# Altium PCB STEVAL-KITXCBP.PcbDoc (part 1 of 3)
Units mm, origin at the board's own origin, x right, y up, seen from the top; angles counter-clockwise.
Board outline 265 x 224 mm, 4 copper layers (Top Layer, GND, PWR, Bottom Layer), stack 1.55 mm thick; 241 components, 114 nets, 595 pads, 236 vias.
Unrouted connection lines stored in the file: 2.
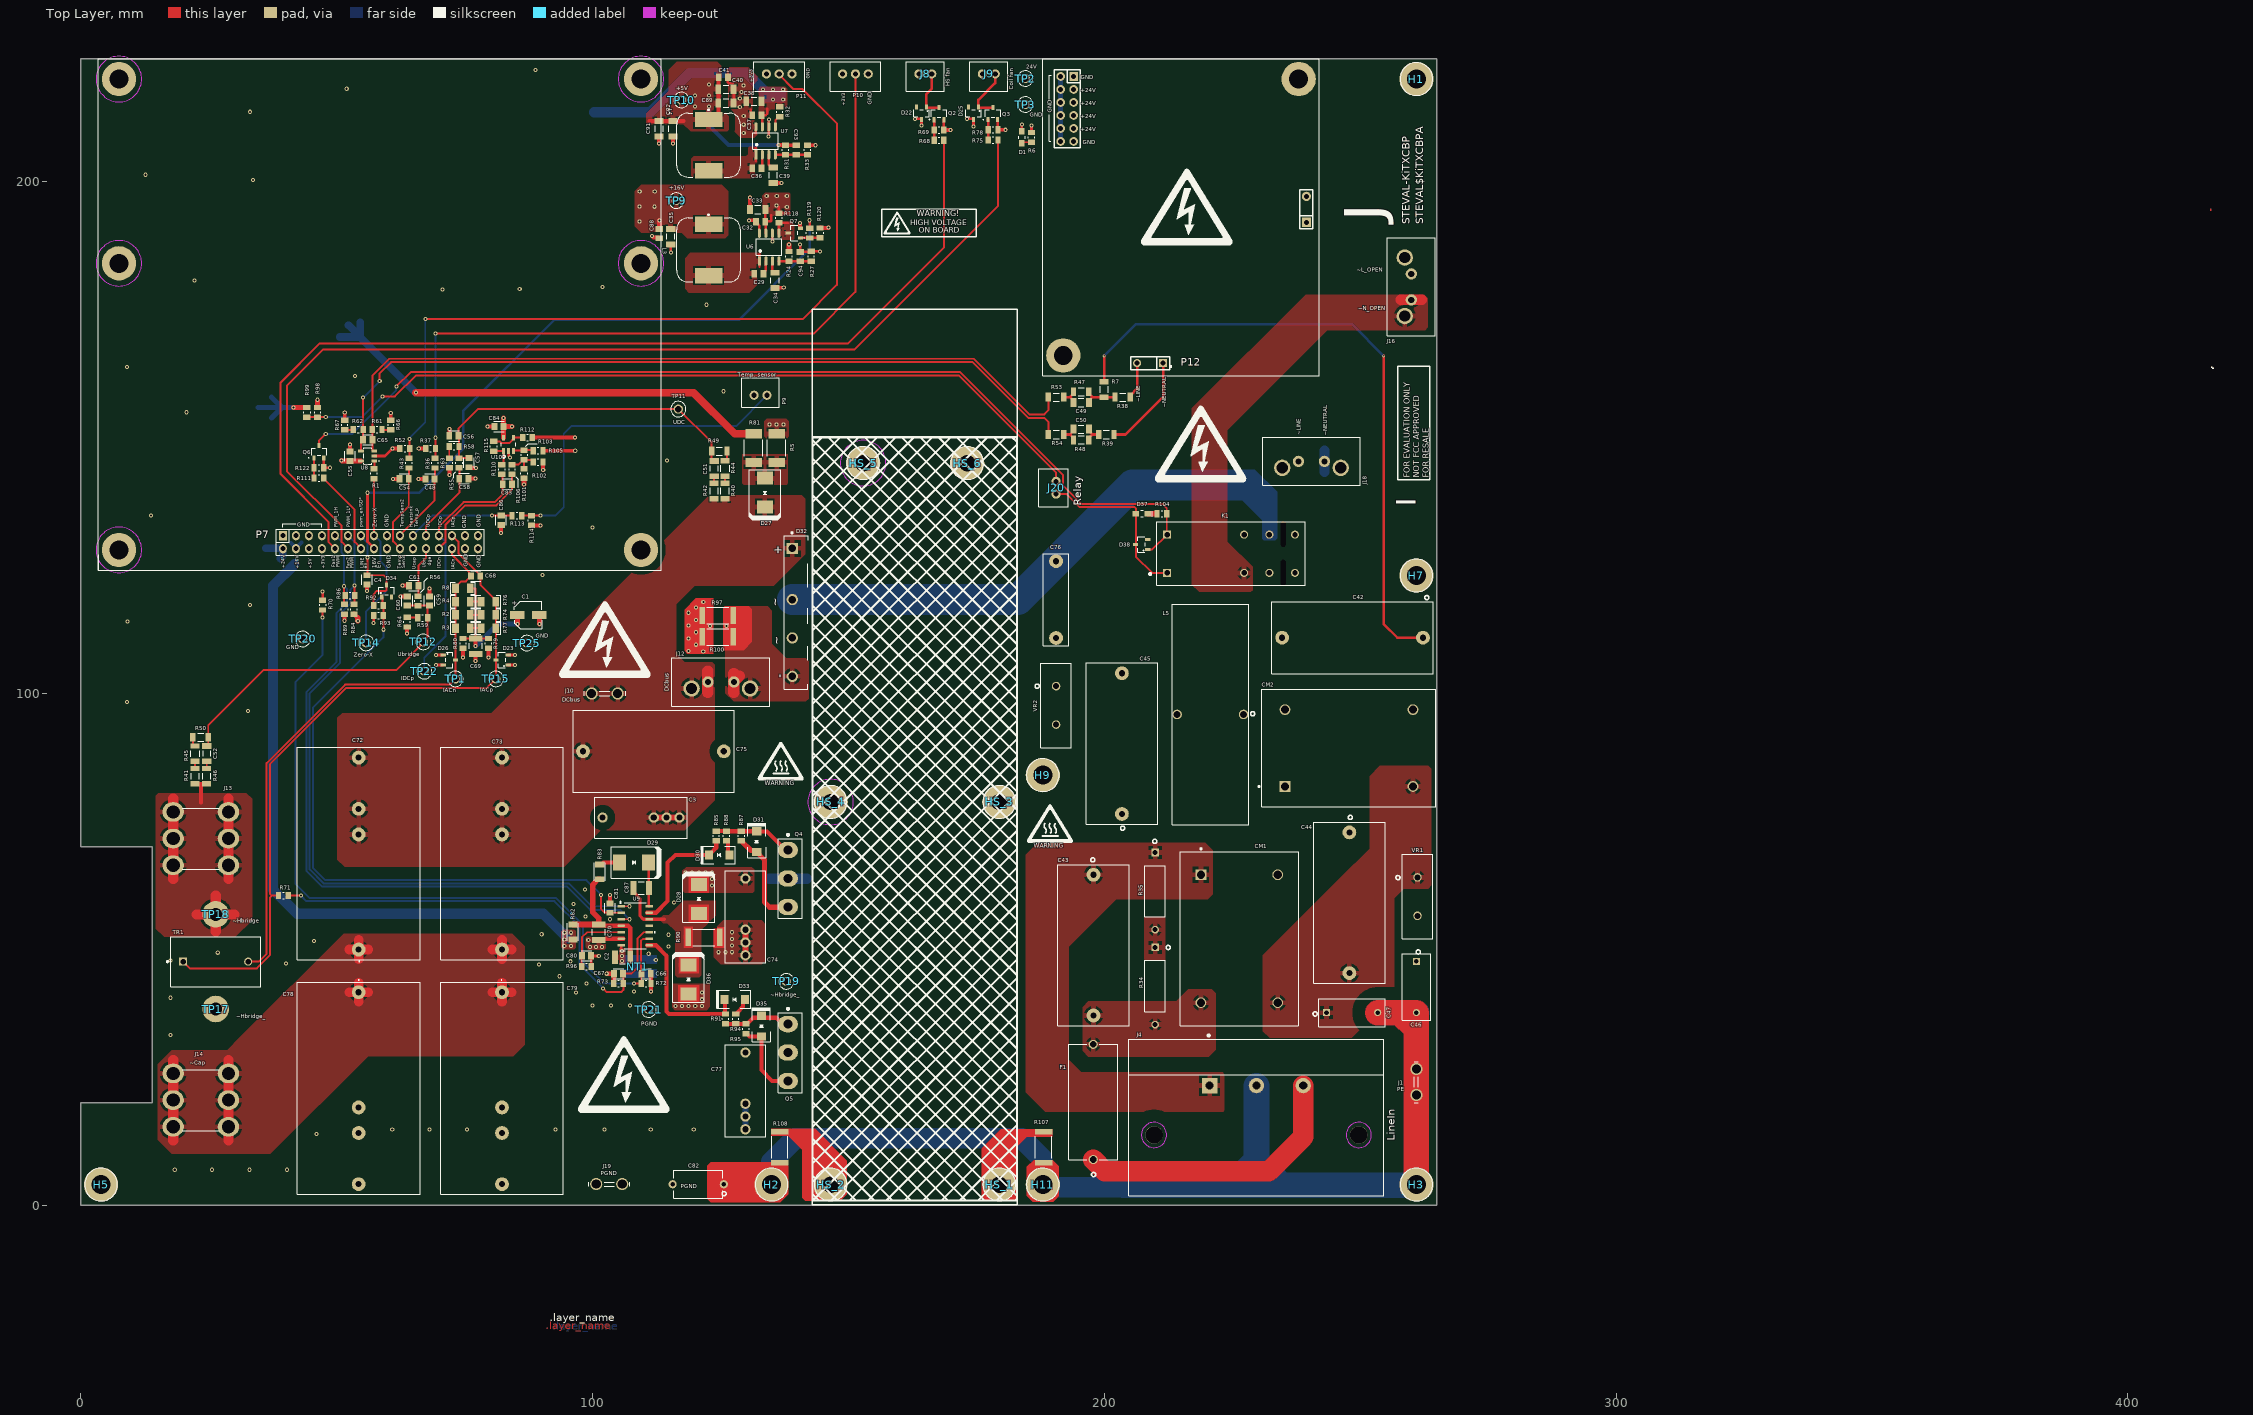
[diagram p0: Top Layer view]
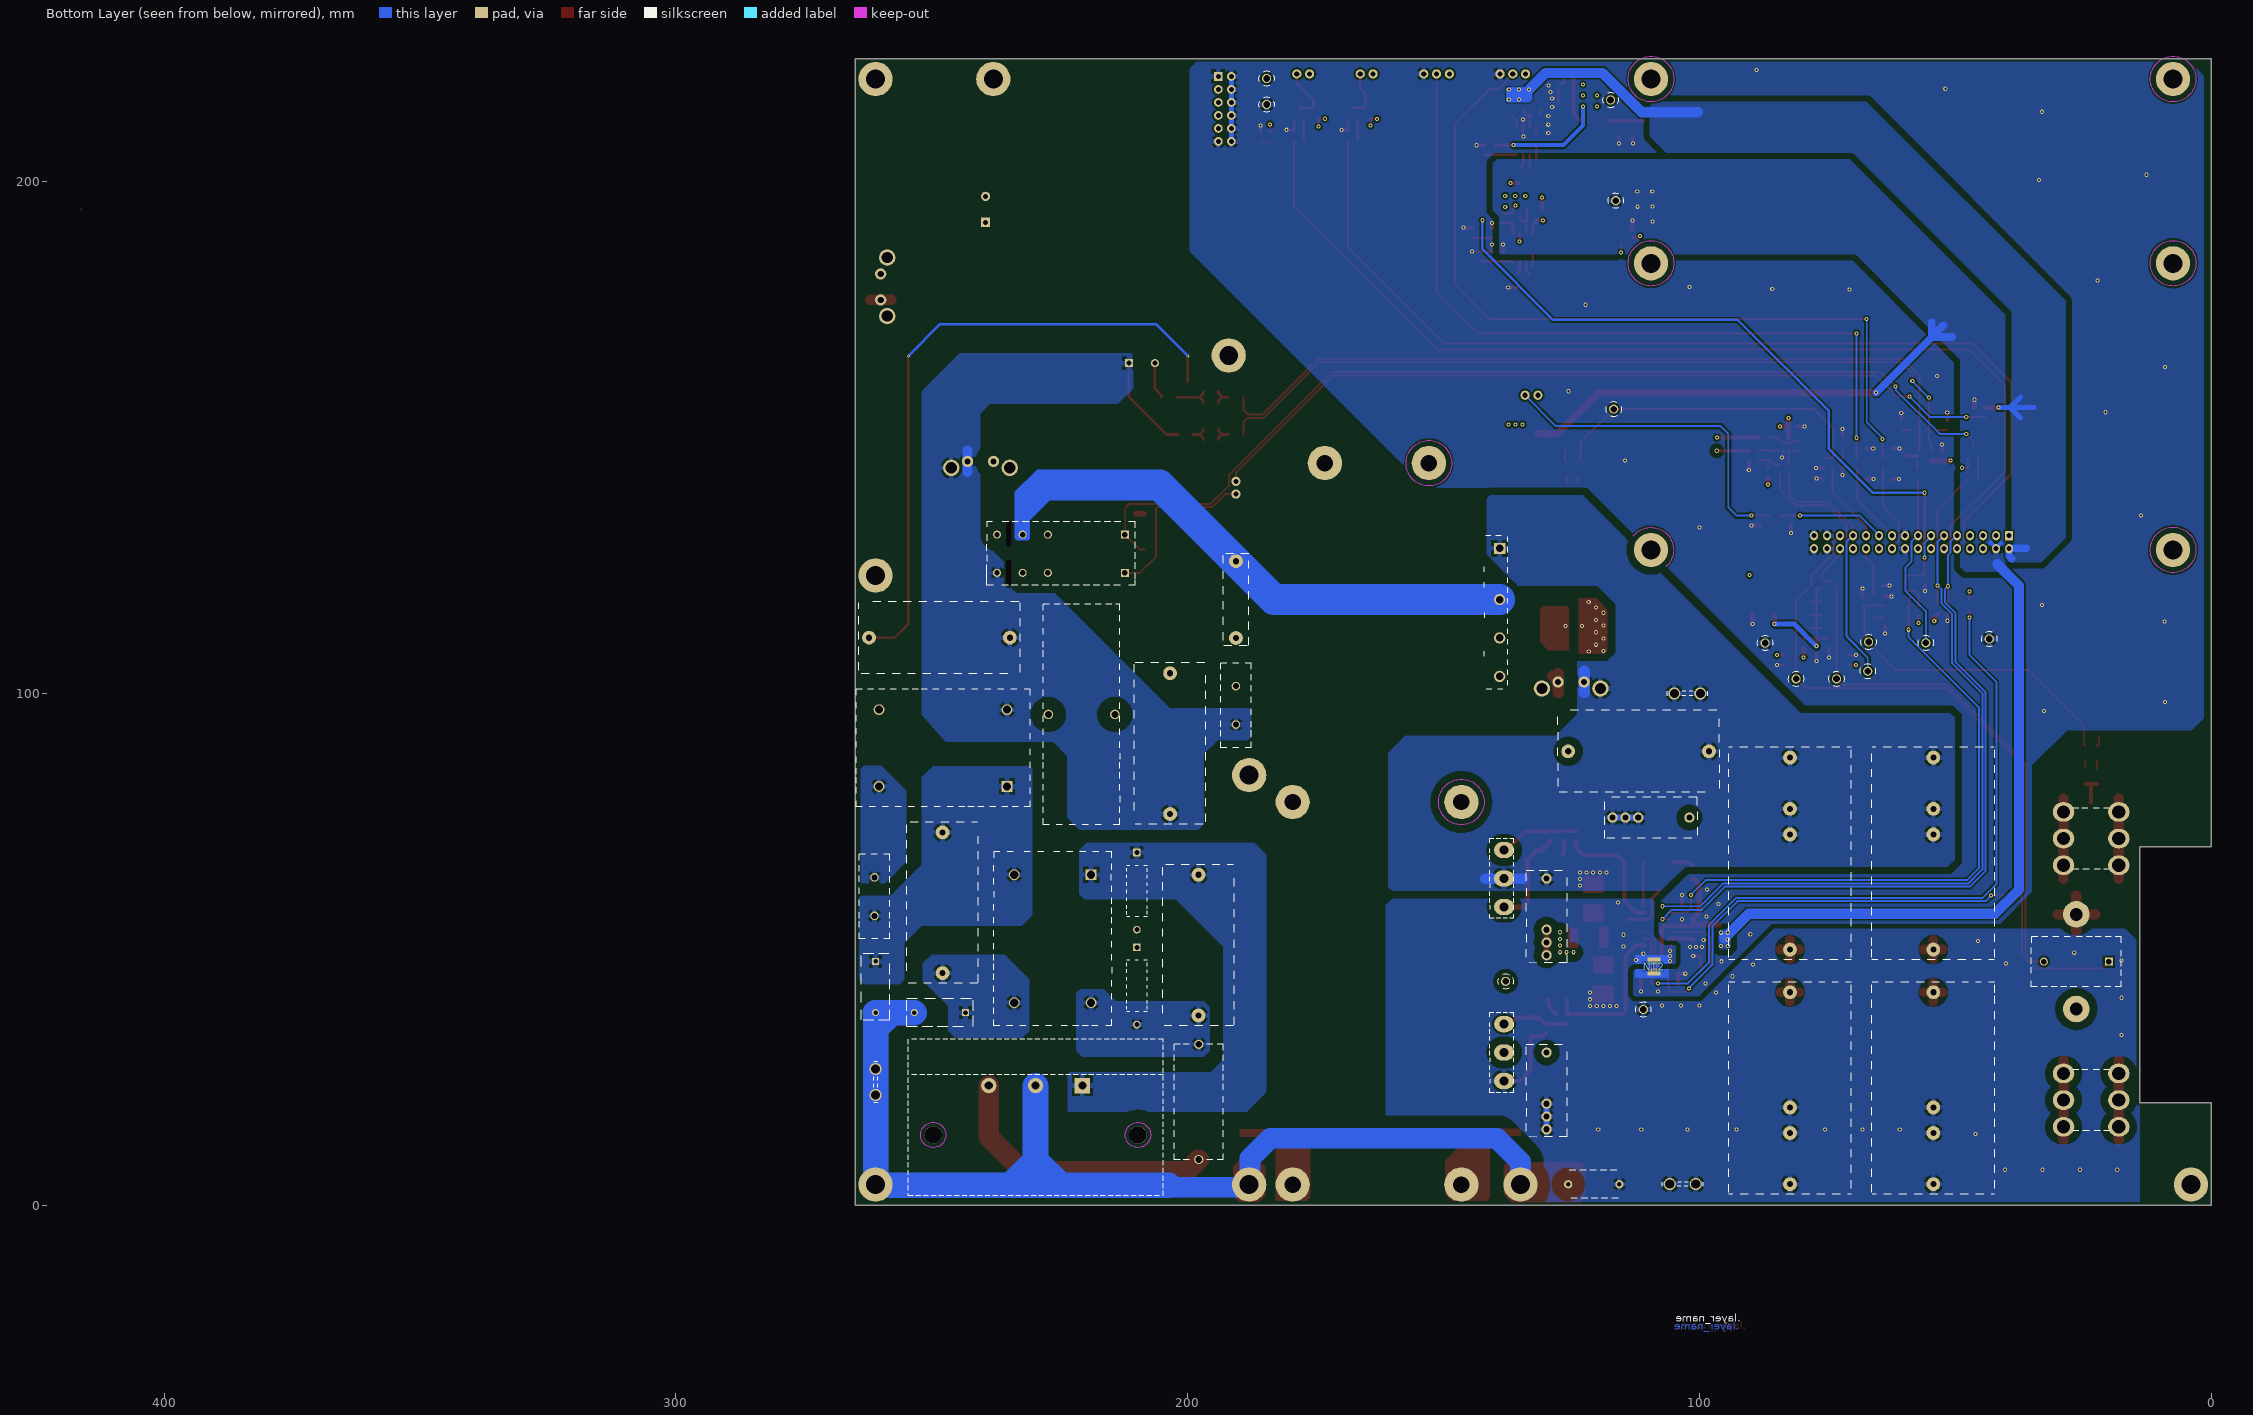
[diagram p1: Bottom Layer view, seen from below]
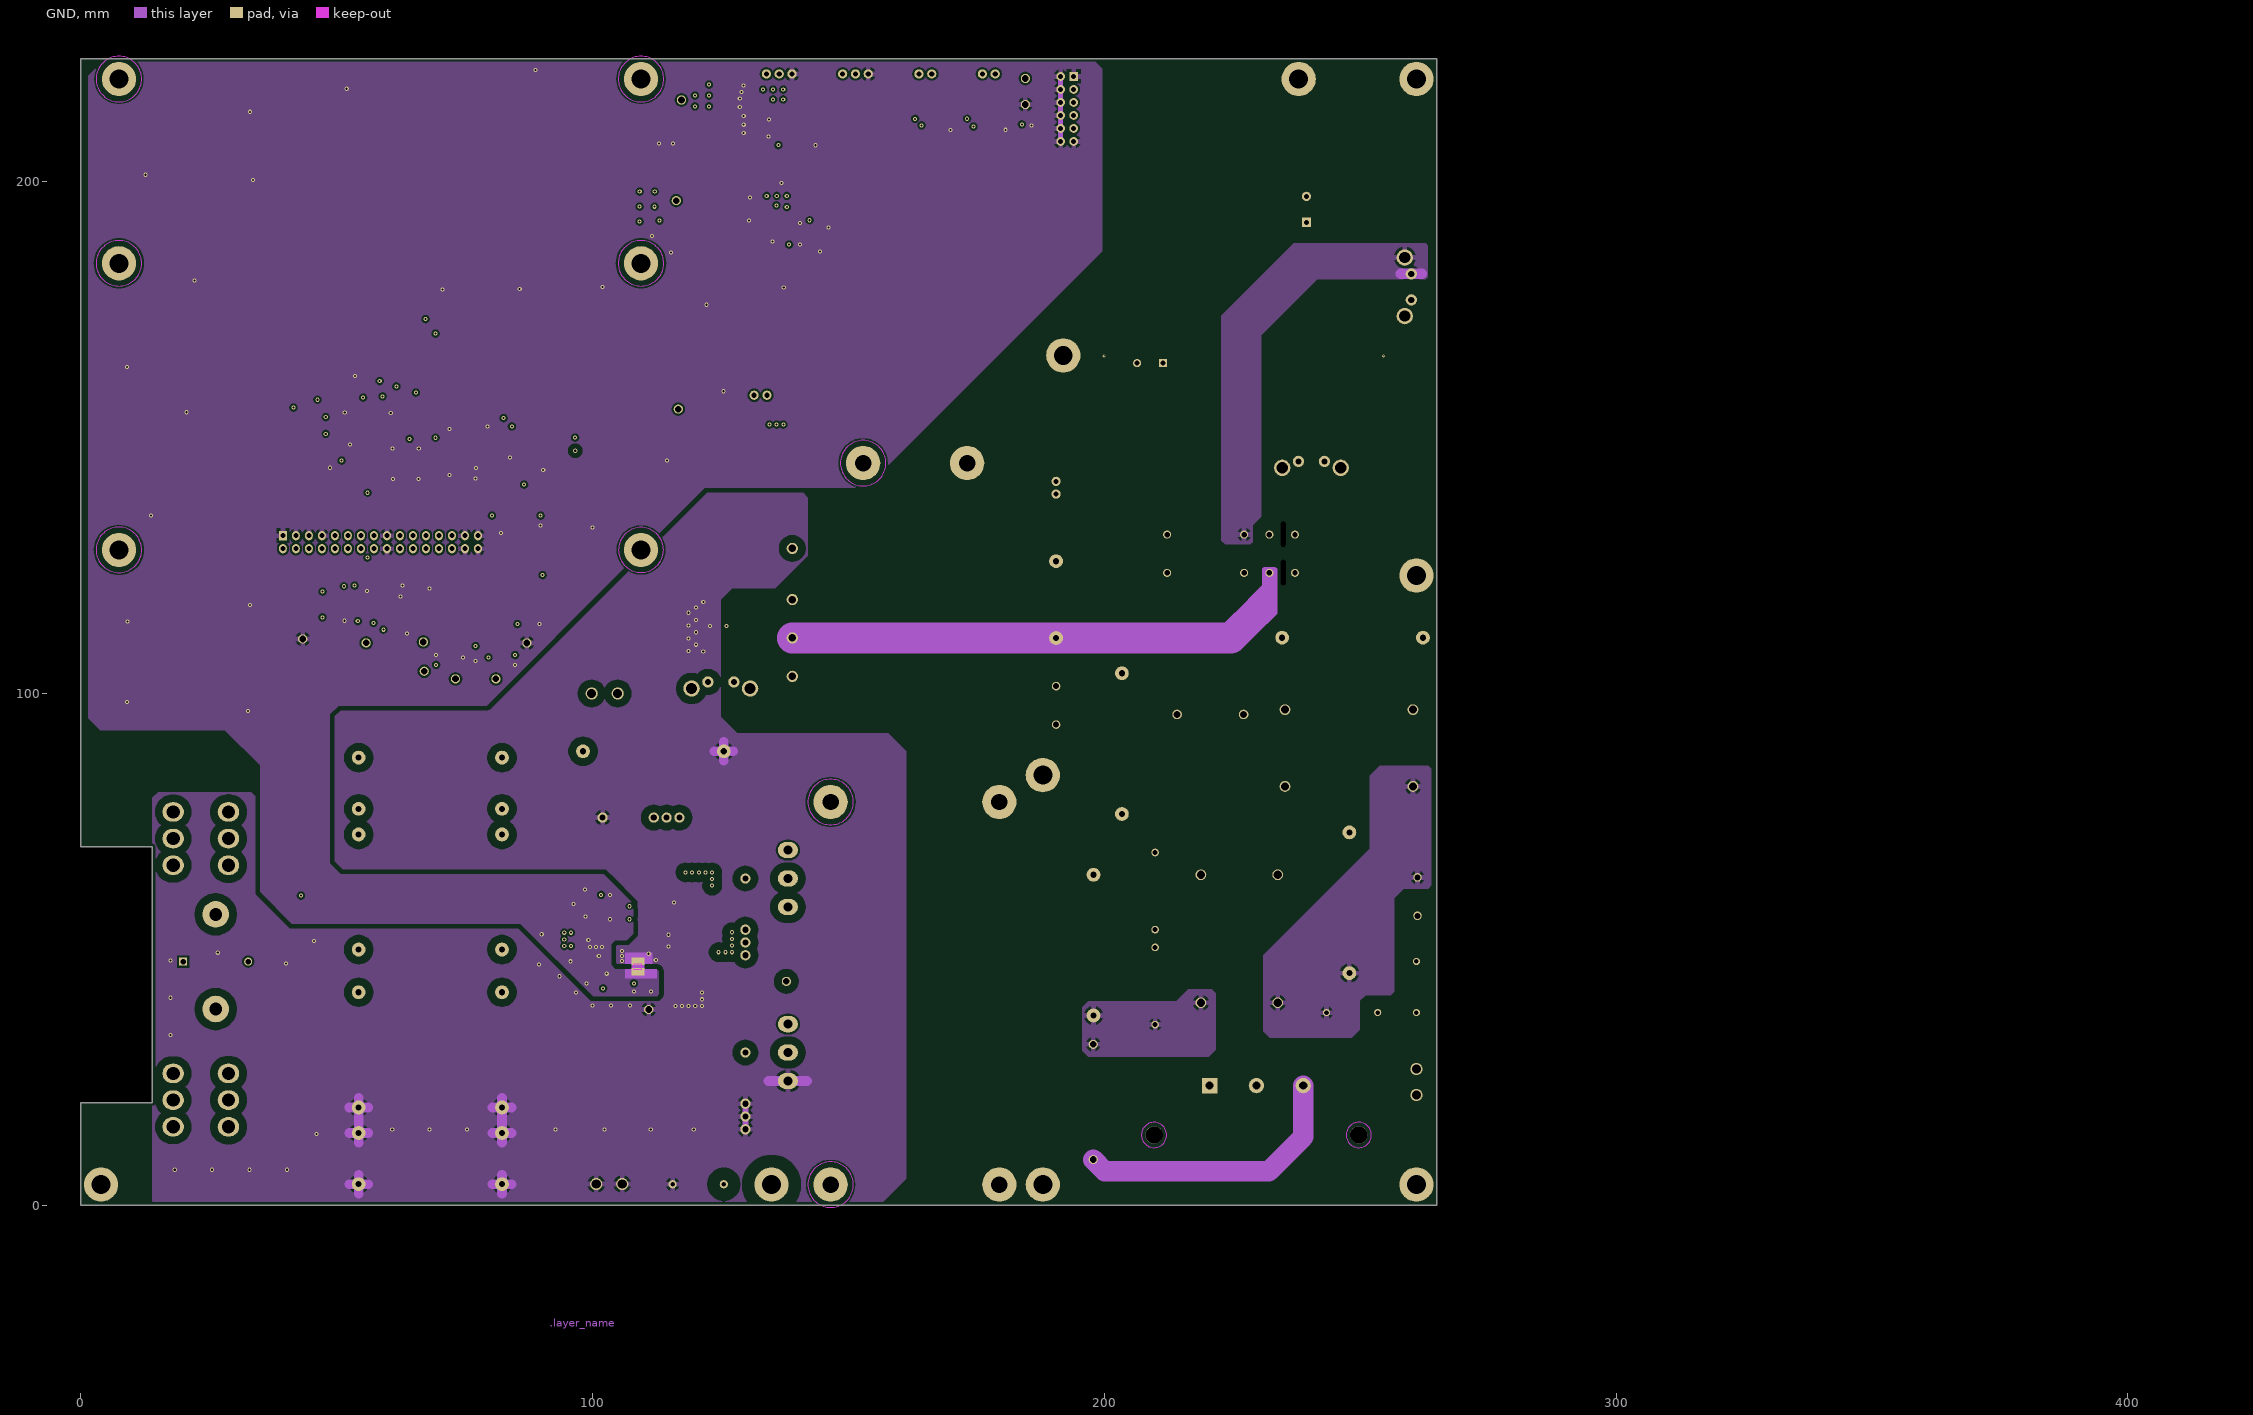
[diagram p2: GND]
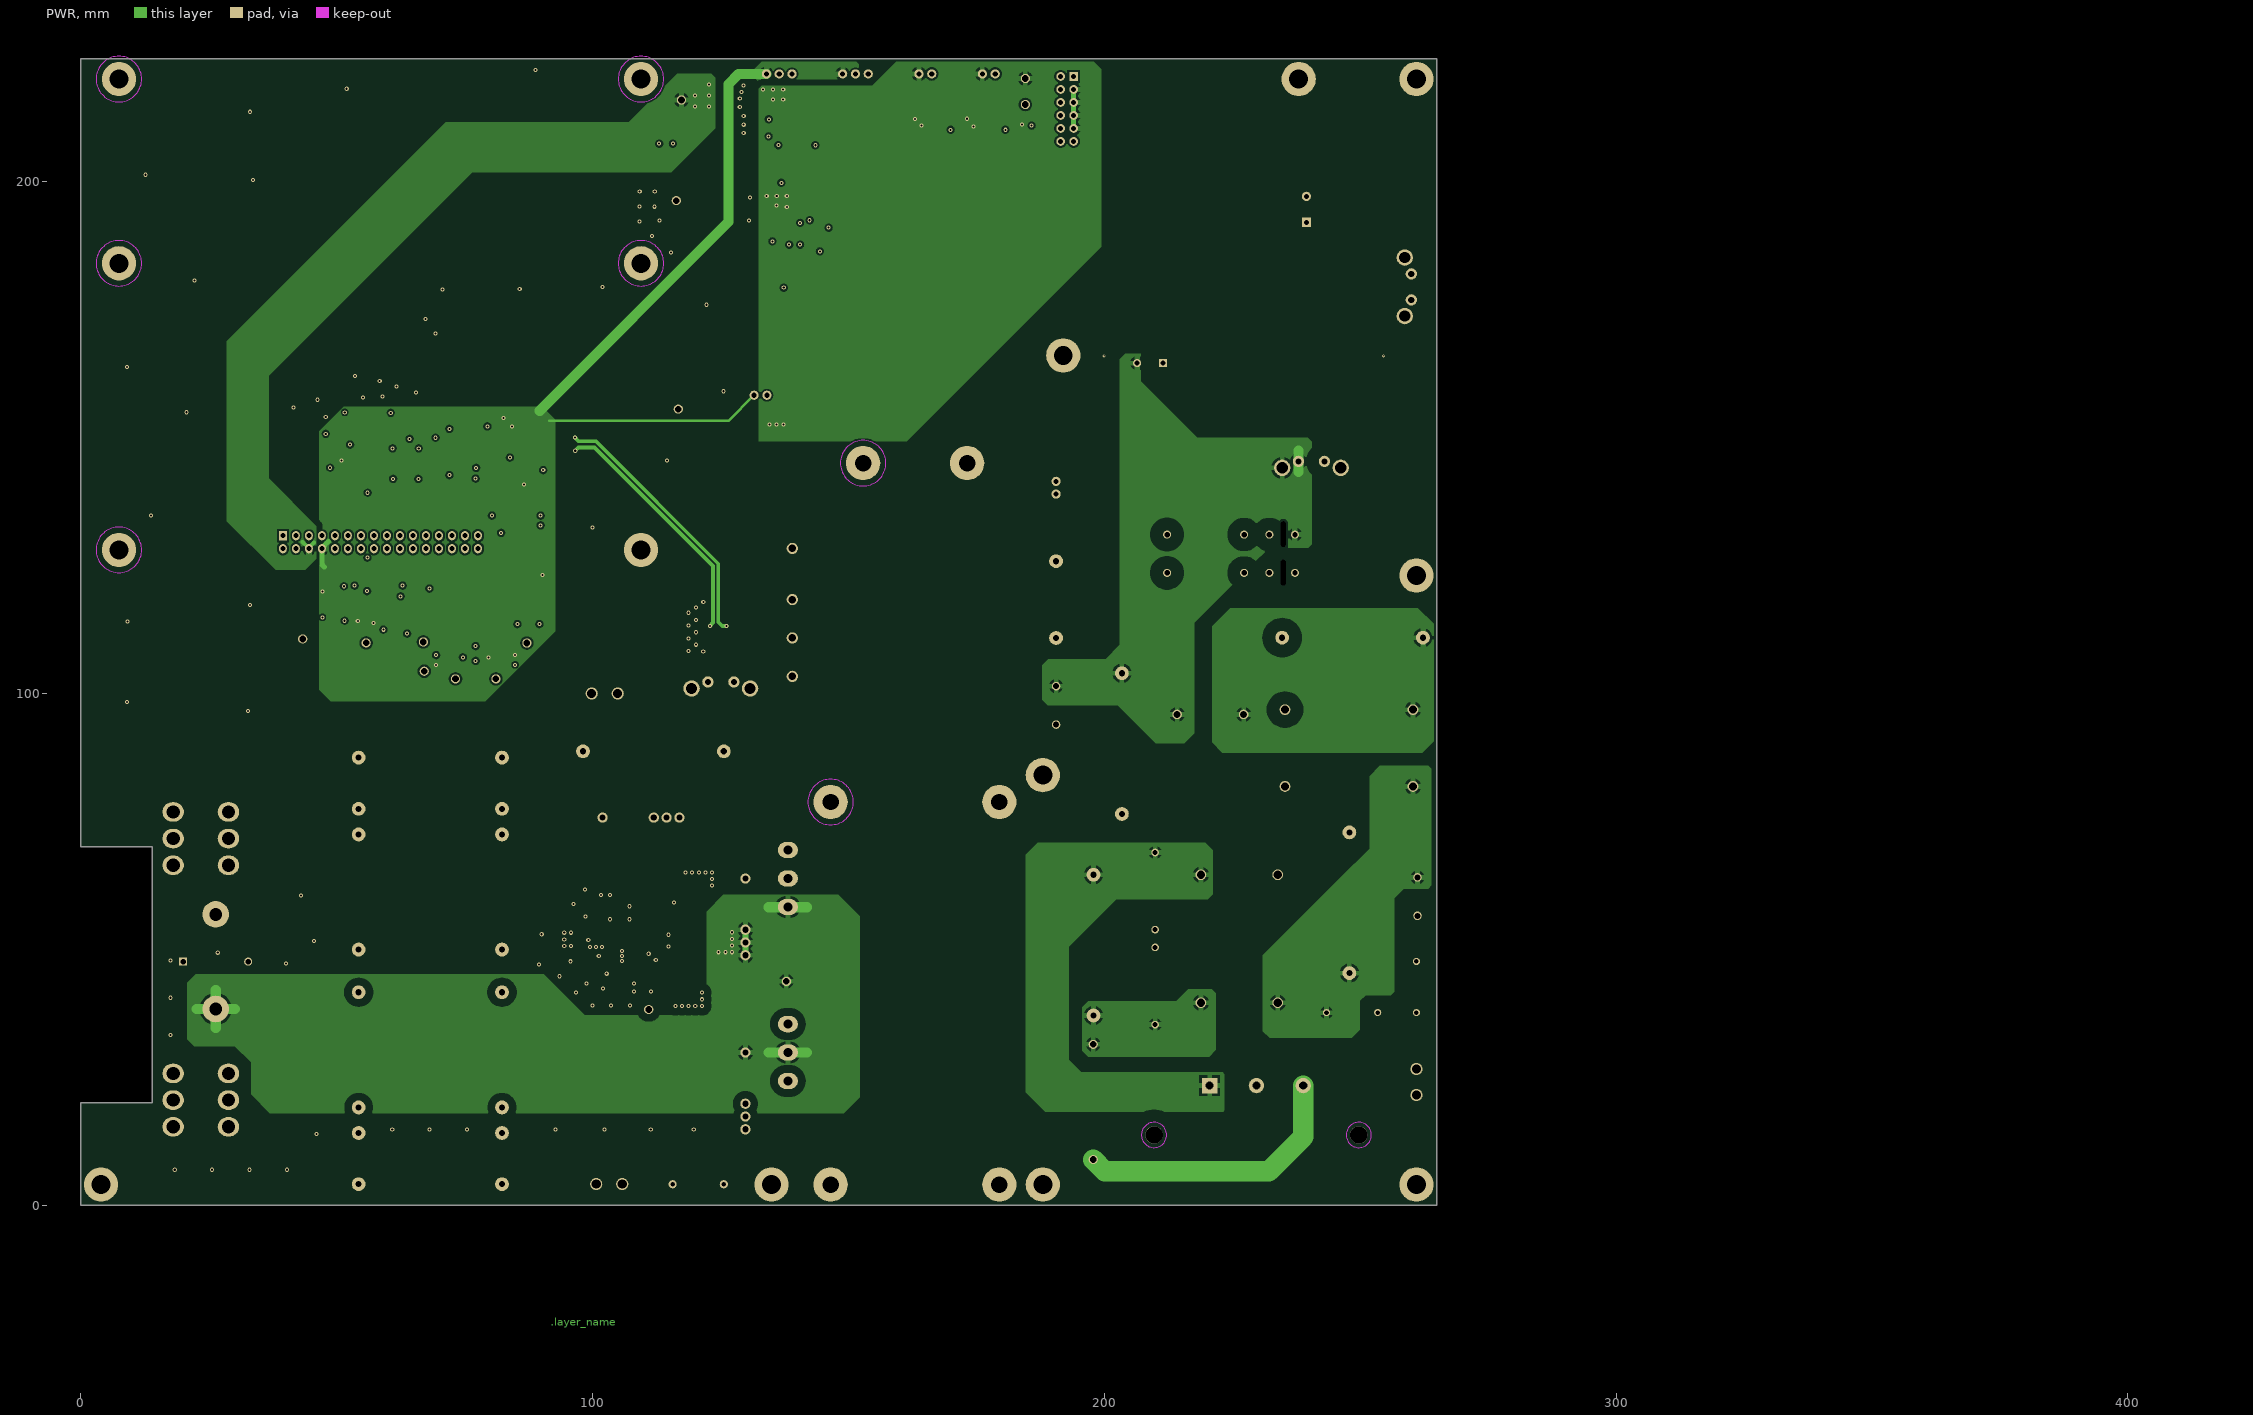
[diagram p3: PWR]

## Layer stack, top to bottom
Top Solder: solder mask 0.0102, Solder Resist, Dk 3.5
Top Layer: signal copper 0.07
Dielectric 1: prepreg 0.381, FR-4 HIGH TG, Dk 4.2
GND: signal copper 0.07
Dielectric 2: dielectric 0.508, FR-4 HIGH TG, Dk 4.2
PWR: signal copper 0.07
Dielectric 3: prepreg 0.381, FR-4 HIGH TG, Dk 4.2
Bottom Layer: signal copper 0.07
Bottom Solder: solder mask 0.0102, Solder Resist, Dk 3.5

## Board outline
0,70 0,224 265,224 265,0 0,0 0,20 14,20 14,70

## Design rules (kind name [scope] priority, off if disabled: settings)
BoardOutlineClearance [All] p1: gap=1.016 ignorepadtopadclearanceinfootprint=FALSE except(0.635: Poly-OutlineEdge)
Clearance "GND clearance" [InNet('GND') vs InNet('~PGND')] p1: gap=0.5 ignorepadtopadclearanceinfootprint=TRUE except(1: Arc-Fill Arc-Poly Arc-Region Track-Fill Track-Poly Track-Region SMDPad-Fill SMDPad-Poly SMDPad-Region THPad-Fill THPad-Poly THPad-Region Via-Fill Via-Poly Via-Region Fill-Fill Fill-Poly Fill-Region Poly-Poly Poly-Region Region-Region)
Clearance "HV clearance" [All vs InNet('~Hbridge') OR InNet('~DCbus') OR InNet('~Hbridge_') OR InNet('~Cap')] p2: gap=1.5 ignorepadtopadclearanceinfootprint=TRUE except(0.85: Arc-SMDPad Track-SMDPad; 1: Arc-Arc Arc-Track Track-Track)
Clearance power_input [InNetClass('ACin')] p3: gap=2.5 ignorepadtopadclearanceinfootprint=FALSE except(0: Fill-Poly; 1.778: Track-SMDPad Track-THPad THPad-THPad; 1.829: SMDPad-SMDPad; 1.854: THPad-Region; 2.032: SMDPad-Region Region-Region; 2.159: Track-Track)
Clearance [All] p4: gap=0.254 ignorepadtopadclearanceinfootprint=FALSE except(0: Arc-SMDPad Arc-Hole Track-Hole SMDPad-Hole THPad-Hole Via-Hole Fill-Hole Poly-Hole Region-Hole Text-Hole; 0.381: Arc-Poly Track-Poly SMDPad-Poly THPad-Poly Via-Poly Fill-Poly; 1.27: Poly-Poly)
ComponentClearance [All] p1: gap=0.508 collisioncheckmode=3 verticalgap=0.508 showdistances=FALSE
Height [All] p1: minheight=0 maxheight=50.8 prefheight=12.7
PlaneConnect [All] p1: planeconnectstyle=Direct reliefexpansion=0.508 reliefentries=4 reliefconductorwidth=0.254 reliefairgap=0.254
PolygonConnect [All] p1: thpad.connectstyle=Relief thpad.reliefconductorwidth=1.016 thpad.reliefentries=4 thpad.polygonreliefangle="90 Angle" thpad.airgapwidth=0.508 smdpad.connectstyle=Relief smdpad.reliefconductorwidth=1.016 smdpad.reliefentries=4 smdpad.polygonreliefangle="90 Angle" smdpad.airgapwidth=0.305 via.connectstyle=Direct via.reliefconductorwidth=0.762 via.reliefentries=4 via.polygonreliefangle="90 Angle" via.airgapwidth=0.508
RoutingVias [All] p1: holewidth=0.508 width=1.016 viastyle="Through Hole" minholewidth=0.508 minwidth=1.016 maxholewidth=0.508 maxwidth=1.016
SolderMaskExpansion [All] p1: expansion=0.102 istentingtop=FALSE
Width [All] p1: maxlimit=6 minlimit=0.254 preferedwidth=0.254 minimp=50.000000 maximp=50.000000 favimp=50.000000
27 further rules are at their usual default settings.

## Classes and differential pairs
component class "C-voltage Regulator": C29 C32 C33 C34 C35 C36 C37 C38 C39 C40 C41 C88 C89 C91 C92 C93 C94 L3 L4 Q7 R24 R27 R31 R32 R33 R118 R119 R120 TP2 TP3 TP9 TP10 U6 U7
net class PriLV: +3V3 CP+ CP- Gnd NetC51_2 NetC52_2 NetC87_1 NetD32_4 NetD33_1 NetD35_2 NetR1_1 NetR58_1 NetR59_1 NetR61_1 NetR62_1 NetR101_1 NetR103_1 NetR110_2 NetR112_2 Ubridge UDC ~Line_sens ~LowDrive ~Neutral_sens ~PGND ~Zero_X
net class Phase: NetC87_1 NetC87_2 NetD29_1 NetD30_1 NetD31_2 NetU9_11 ~Cap ~DCbus ~Hbridge ~Hbridge_ ~HighDrive
net class PE: HS_1 HS_2 HS_3 PE01 PE03 PE04 PE05 PE11 PE12
net class HV: ~DCbus
net class ACin: NetC44_1 NetC44_2 NetF1_1 NetR34_1 PE03 ~AC_L ~AC_N ~Line ~Line_pf ~Neutral
component class "B-Power Stage": C1 C2 C3 C4 C48 C49 C50 C51 C52 C54 C55 C56 C57 C58 C59 C60 C61 C65 C66 C67 C68 C69 C70 C72 C73 C74 C75 C76 C77 C78 C79 C80 C81 C82 C83 C84 C86 C87 D1 D22 D23 D25 D26 D27 D28 D29 D30 D31 D32 D33 D34 D35 D36 D37 D38 H1 H2 H3 H5 H7 H9 H11 HS1 HS_1 HS_2 HS_3 HS_4 HS_5 HS_6 J1 J8 J9 J10 J12 J13 J14 J16 J18 J19 J20 K1 NT1 NT2 P7 P9 P10 P11 P12 Q2 Q3 Q4 Q5 Q6 R1 R2 R3 R4 R5 R6 R7 R8 R36 R37 R38 R39 R40 R41 R42 R43 R44 R45 R46 R47 R48 R49 R50 R52 R53 R54 R55 R56 R58 R59 R61 R62 R63 R64 R66 R67 R68 R69 R70 R71 R72 R73 R74 R75 R76 R77 R78 R79 R80 R81 R82 R83 R84 R85 R86 R87 R88 R89 R90 R91 R92 R93 R94 R95 R96 R97 R98 R99 R100 R101 R102 R103 R104 R105 R106 R107 R108 R110 R111 R112 R113 R114 R115 R122 TP1 TP11 TP12 TP14 TP15 TP17 TP18 TP19 TP20 TP21 TP22 TP25 TR1 U8 U9 U10
component class "A-Input Mains Filter": C42 C43 C44 C45 C46 C47 CM1 CM2 F1 J4 L5 R34 R35 VR1 VR2

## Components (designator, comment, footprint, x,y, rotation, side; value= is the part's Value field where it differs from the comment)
C1 "47u" "ELCAP SMD D5H5.8P1.5" 87.482,115.3 r270 top value=47uF
C2 "10uF/50V" CC1210 105.9,48.4 r0 top value=10u/50V
C3 "NM" CAPRR1500W80L1800T800H1500A 117,75.7 r180 top value=10n
C4 "10n" CC0805 55.969,122.147 r270 top
C29 "100nF" CAP_0805J_AVX#1 132.514,181.968 r180 top
C32 "1uF" CAP_0805J_AVX#2 132.884,192.101 r0 top
C33 "10uF/50V" CC1206 132.3,194.513 r0 top
C34 "1uF/25V" CC1206 135.668,180.659 r90 top
C35 "22uF" CC1206 115.3,189.2 r90 top
C36 "100nF" CAP_0805J_AVX#1 132.128,202.542 r180 top
C37 "1uF" CAP_0805J_AVX#1 132.145,212.95 r0 top
C38 "10uF/50V" CC1206 131.572,215.646 r0 top
C39 "1uF/25V" CC1206 135.316,201.202 r90 top
C40 "10uF" CC1206 126.1,218 r180 top
C41 "100nF" CAP_0805J_AVX#2 125.578,220.32 r180 top
C42 "2u2" CAPRR2750W80L3150T1400H2450A 262.268,110.848 r180 top
C43 "2u2" CAPRR2750W80L3150T1400H2450A 197.913,64.536 r270 top
C44 "2u2" CAPRR2750W80L3150T1400H2450A 247.9,72.816 r270 top
C45 "NM" CAPRR2750W80L3150T1400H2450A 203.45,76.406 r90 top value=2u2
C46 "4n7" CAPPRD1000W60D1300T550H1700 261,47.6 r270 top value=4n7/Y1
C47 "4n7" CAPPRD1000W60D1300T550H1700 243.43,37.6 r0 top value=4n7/Y1
C48 "10n" CC0805 68.274,141.858 r180 top
C49 "100p" CC1206 195.5,156.8 r0 top
C50 "100p" CC1206 195.5,151.6 r0 top
C51 "100p" CC1206 123.8,143.9 r90 top
C52 "100p" CC1206 24.65,88.2 r90 top
C54 "10n" CC0805 63.22,141.872 r180 top
C55 "100n" CC0805 52.648,146.306 r90 top
C56 "10n" CC0805 72.944,150.266 r180 top
C57 "2n2" CC0805 75.896,145.04 r270 top
C58 "NM" CC0805 74.895,141.93 r0 top
C59 "10n" CC0805 68.169,118.033 r90 top
C60 "2n2" CC0805 63.801,118.033 r90 top
C61 "NM" CC0805 65.099,121.03 r180 top
C65 "1n" CC0805 56.102,149.531 r180 top
C66 "100n" CC0805 110.5,45.2 r0 top
C67 "470p" CC0805 105.1,45.2 r180 top
C68 "10n" CC0805 77.2,122.9 r180 top
C69 "4u7/50V" CC1210 77.2,109.2 r270 top
C70 "10uF/50V" CC1210 101.252,53.303 r90 top value=10u/50V
C72 "160n/1000V" "Capacitor  Non-Polarised" 54.334,49.913 r180 top locked value=2u2
C73 "NM" "Capacitor  Non-Polarised" 82.338,49.913 r180 top locked value=2u2
C74 "4n7" CAPRR1500W80L1800T800H1500A 129.9,63.8 r270 top
C75 "3u3/650V" CAPRR2750W80L3150T1600H3200A 98.175,88.65 r0 top value=3u3
C76 "100nF" CAPRR1500W80L1800T500H1050A 190.6,125.797 r270 top
C77 "4n7" CAPRR1500W80L1800T800H1500A 129.9,29.8 r270 top
C78 "160nF/1000V" "Capacitor  Non-Polarised" 54.334,41.579 r0 top locked value=2u2
C79 "NM" "Capacitor  Non-Polarised" 82.338,41.579 r0 top locked value=2u2
C80 "100n" CC0805 98.852,48.687 r0 top
C81 "100n" CC0805 103.448,58.013 r90 top
C82 "2n2" CAPRB1000W60L950T550H1350 125.679,4.064 r180 top value=2n2/Y1
C83 "10n" CC0805 83.38,140.866 r180 top
C84 "100n" CC0805 81.769,152.119 r0 top
C86 "100n" CC0805 82.166,133.789 r270 top
C87 "330n/50V" CC1210 109.552,61.93 r0 top value=4u7/50V
C88 "100nF" CAP_0805J_AVX#2 113.1,189.8 r90 top
C89 "10uF" CC1206 126.1,215.3 r180 top
C91 "10uF" CC1206 113.039,210.277 r90 top
C92 "10uF" CC1206 115.731,210.277 r90 top
C93 "10pF" CAP_0805J_AVX#1 139.837,206.136 r90 top
C94 "NM" CAP_0805J_AVX#2 140.578,185.321 r270 top
CM1 "WE-CMBNC" WE_7448051012 218.893,64.525 r270 top value=12mH/10A
CM2 "WE-CMBNC" WE_7448051012 235.321,81.79 r0 top value=12mH/10A
D1 "KPT-2012SGC" LED_KPT-2012EC 183.9,208.6 r270 top
D22 "BAT54S" SOT23_3 164.307,213.308 r180 top
D23 "BAT54S" SOT23_3 82.35,106.5 r90 top
D25 "BAT54S" SOT23_3 174.458,213.327 r180 top
D26 "BAT54S" SOT23_3 72.05,106.5 r270 top
D27 "STTH3R06S" DO214AB-SMC 133.7,139.2 r270 top
D28 "STTH3R06S" DO214AB-SMC 120.8,59.8 r90 top
D29 "STTH3R06S" DO214AB-SMC 108.152,66.93 r0 top
D30 "STPS1L30A" DO214AC-SMA 124.8,68.4 r180 top
D31 "SMAJ15A" DO214AC-SMA 132.1,71 r90 top
D32 "GSIB2560" SIP_GSIB2560-E3/45 139.062,128.297 r270 top
D33 "STPS1L30A" DO214AC-SMA 127.816,40.184 r180 top
D34 "BAT54S" SOT23_3 59.8,119.979 r0 top
D35 "SMAJ15A" DO214AC-SMA 133.016,34.972 r90 top
D36 "STTH3R06S" DO214AB-SMC 118.8,44.1 r90 top
D37 "KPT-2012EC" LED_KPT-2012EC 207.356,135.074 r0 top
D38 "BAT54S" SOT23_3 207.3,129.068 r90 top
F1 "10A" FUSEHOLDER_31.8201 197.851,8.892 r90 top value=FuseHolder
H1 "Hole" HOLE_M3#1 261,220 r0 top
H2 "Hole" HOLE_M3#1 135,4 r0 top
H3 "Hole" HOLE_M3#1 261,4 r0 top
H5 "Hole" HOLE_M3#1 4,4 r0 top
H7 "Hole" HOLE_M3#1 261,123 r0 top
H9 "Hole" HOLE_M3#1 188,84 r0 top
H11 "Hole" HOLE_M3#1 188,4 r0 top
HS_1 "Hole" HOLE_M3#2 179.512,4 r0 top
HS_2 "Hole" HOLE_M3#2 146.543,4 r0 top
HS_3 "Hole" HOLE_M3#2 179.512,78.753 r0 top
HS_4 "Hole" HOLE_M3#2 146.543,78.753 r0 top
HS_5 "Hole" HOLE_M3#2 152.893,144.965 r0 top
HS_6 "Hole" HOLE_M3#2 173.213,144.965 r0 top
J1 "Faston" TE_726386-2 261,24.031 r270 top
J4 "LineIn" BULGIN_PX0580/PC 229.739,13.693 r0 top value=PX0580PC
J8 "HS fan" "CONNECTOR P2.5 MALE" 165.05,221 r0 top value=B2B-XH-A
J9 "Coil fan" "CONNECTOR P2.5 MALE" 177.45,221 r0 top value=B2B-XH-A
J10 "Faston" TE_726386-2 102.4,99.953 r180 top
J12 "DCbus" "Connector P5.08" 125.1,102.2 r0 top
J13 "7807" KEYSTONE_7807 23.5,71.6 r180 top
J14 "7807" KEYSTONE_7807 23.5,20.5 r180 top
J16 "Line open" "Connector P5.08" 260,179.4 r270 top
J18 "ACline" "Connector P5.08" 240.486,145.3 r0 top
J19 "Faston" TE_726386-2 103.287,4.097 r180 top
J20 "Relay" "CONNECTOR P2.5 MALE" 190.6,140.15 r270 top value=B2B-XH-A
K1 "Main power" RELAY_40.62.7.024.4000 224.775,127.256 r0 top value=40.62.7.024.4000
L3 "47uH" WE-PD_1260 122.7,186.6 r180 top
L4 "33uH" WE-PD_1260 122.7,207.1 r180 top
L5 "MCAP115018047A-221MU" MULTICOMP_MCAP115018047A-221MU 220.747,95.849 r90 top
NT1 "Net-Tie" Net-Tie_0805_HV_NoOverlay#1 108.9,46.6 r270 top net-tie
NT2 "NET-TIE" Net-Tie_0805_HV_NoOverlay#2 108.9,46.6 r270 bottom net-tie
P7 "MCU Board" "ST MCU BOARD" 58.59,129.51 r0 top locked
P9 "B2B-XH-A(LF)(SN)" "CONNECTOR P2.5 MALE" 132.85,158.225 r180 top
P10 "B3B-XH-A(LF)(SN)" "CONNECTOR P2.5 MALE 3WAY" 151.4,221 r0 top
P11 "B3B-XH-A(LF)(SN)" "CONNECTOR P2.5 MALE 3WAY" 136.5,221 r0 top
P12 "AUX Supply" "ST AUX SUPPLY" 242,162 r90 top locked
Q2 "2STR1160" SOT23_3 167.726,213.255 r0 top
Q3 "2STR1160" SOT23_3 178.241,213.274 r0 top
Q4 "STGWA50IH65DF" TO-247-3P 138.2,69.36 r270 top
Q5 "STGWA50IH65DF" TO-247-3P 138.2,35.36 r270 top
Q6 "2STR1160" SOT23_3 46.564,147.185 r0 top
Q7 "2STR1160" SOT23_3 139.461,189.893 r90 top
R1 "100R" RC0805 57.353,142.885 r270 top
R2 "5E6/0.25W" VSMP_1206 74.7,115.3 r0 top
R3 "5E6/0.25W" VSMP_1206 74.7,112.7 r180 top
R4 "5E6/0.25W" VSMP_1206 74.7,117.9 r0 top
R5 "NM" VSMP_2512 136,147.9 r270 top
R6 "10k" RC0805 185.8,208.6 r270 top
R7 "NM" RC1206 200,159.35 r270 top value=681kR
R8 "NM" VSMP_1206 74.7,120.5 r180 top
R24 "150k" RC0805 138.445,185.356 r90 top
R27 "8.2k" RC0805 142.763,185.372 r270 top
R31 "402k" RC0805 137.704,206.136 r90 top
R32 "10k" RC0805 136.6,213.6 r270 top
R33 "82k" RC0805 142.001,206.136 r270 top
R34 "1M/VR37" RESAD1508W70L1000D400A 209.952,50.338 r270 top
R35 "1M/VR37" RESAD1508W70L1000D400A 209.952,68.88 r270 top
R36 "3K3" RC0805 69.249,144.945 r90 top
R37 "100K" RC0805 68.399,147.827 r0 top
R38 "680k" RC1206 203.6,157.85 r0 top value=681kR
R39 "680k" RC1206 200.4,150.55 r180 top value=681kR
R40 "680k" RC1206 125.9,139.5 r270 top value=681kR
R41 "680k" RC1206 22.35,83.8 r270 top value=681kR
R42 "1k5" RC1206 123.8,139.5 r270 top
R43 "3K3" RC0805 64.195,144.959 r90 top
R44 "680k" RC1206 125.9,143.9 r270 top value=681kR
R45 "680k" RC1206 22.35,88.2 r270 top value=681kR
R46 "1k5" RC1206 24.65,83.8 r270 top
R47 "680k" RC1206 195.5,158.9 r0 top value=681kR
R48 "680k" RC1206 195.5,149.5 r180 top value=681kR
R49 "680k" RC1206 124.8,147.3 r0 top value=681kR
R50 "680k" RC1206 23.45,91.4 r180 top value=681kR
R52 "100K" RC0805 63.345,147.841 r0 top
R53 "680k" RC1206 190.6,157.85 r0 top value=681kR
R54 "680k" RC1206 190.6,150.55 r180 top value=681kR
R55 "68R" RC0805 73.929,144.99 r90 top
R56 "68R" RC0805 65.934,118.033 r270 top
R58 "15k" RC0805 72.979,148.23 r0 top
R59 "15k" RC0805 66.849,114.731 r0 top
R61 "27k" RC0805 57.952,151.503 r180 top
R62 "27k" RC0805 54.252,151.503 r0 top
R63 "470R" RC0805 72.065,144.99 r270 top
R64 "470R" RC0805 63.815,113.883 r270 top
R66 "1k" RC0805 60.604,152.405 r270 top
R67 "1k" RC0805 51.613,152.405 r90 top
R68 "470R" RC0805 167.71,208.044 r180 top
R69 "47K" RC0805 167.71,210.065 r180 top
R70 "3k3" RC0805 47.3,117.2 r90 top
R71 "3k3" RC0805 39.628,60.448 r180 top
R72 "10k" RC0805 110.5,43.3 r180 top
R73 "10k" RC0805 105.1,43.3 r0 top
R74 "5E6/0.25W" VSMP_1206 79.7,115.3 r0 top
R75 "470R" RC0805 178.31,208.063 r180 top
R76 "5E6/0.25W" VSMP_1206 79.7,117.9 r180 top
R77 "5E6/0.25W" VSMP_1206 79.7,112.7 r0 top
R78 "47K" RC0805 178.31,210.084 r180 top
R79 "1k" RC0805 79.7,109.75 r270 top
R80 "1k" RC0805 74.7,109.75 r270 top
R81 "NM" VSMP_2512 131.5,147.9 r270 top
R82 "3R3" "RES SMD 1206" 96.2,53.35 r270 top
R83 "3R3" "RES SMD 1206" 101.425,65.1 r90 top
R84 "NM" RC0805 53.45,116.4 r270 top
R85 "22R" RC0805 124.2,72.1 r90 top
R86 "NM" RC0805 52.633,119.094 r0 top
R87 "10k" RC0805 129.1,72.1 r270 top
R88 "4R7" RC0805 126.2,72.1 r270 top
R89 "NM" RC0805 51.6,116.4 r90 top
R90 "R680/3W" RC2512 121.8,52.3 r180 top value=R680
R91 "22R" RC0805 126.016,36.369 r270 top
R92 "1K" RC0805 58.2,117.155 r0 top
R93 "10k" RC0805 58.2,115.196 r180 top
R94 "4R7" RC0805 128.016,36.369 r90 top
R95 "10k" RC0805 130.016,34.439 r270 top
R96 "33K" RC0805 98.852,46.63 r0 top
R97 "R030/3W" RC2512 124.495,115.181 r0 top value=R030
R98 "NM" RC0805 46.288,154.882 r90 top
R99 "0R" RC0805 44.205,154.882 r90 top
R100 "R030/3W" RC2512 124.495,111.015 r0 top value=R030
R101 "2k2" RC0805 86.656,142.944 r270 top
R102 "68R" RC0805 89.411,145.191 r180 top
R103 "10k" RC0805 86.656,146.539 r270 top
R104 "10k" RC0805 211.268,135.074 r180 top
R105 "1k" RC0805 89.411,147.389 r180 top
R106 "0R" RC0805 84.275,143.718 r90 top
R107 "0E" RC2512 188.148,11.282 r90 top
R108 "0E" RC2512 136.6,11.3 r90 top
R110 "68R" RC0805 82.306,143.718 r90 top
R111 "470R" RC0805 46.564,142.069 r180 top
R112 "1k" RC0805 87.312,149.959 r180 top
R113 "10k" RC0805 85.253,134.689 r180 top
R114 "33K" RC0805 88.1,133.739 r270 top
R115 "10k" RC0805 80.713,148.245 r270 top
R118 "10k" RC0805 136.449,192.837 r90 top
R119 "1k" RC0805 142.458,189.893 r90 top
R120 "10k" RC0805 144.49,189.944 r270 top
R122 "10k" RC0805 46.564,144.05 r180 top
TP1 "IACn" TP_20-313142 73.25,102.8 r90 top value="Test Point"
TP2 "24V" TP_20-313142 184.6,220.1 r180 top value="Test Point"
TP3 "GND" TP_20-313142 184.601,215.02 r180 top value="Test Point"
TP9 "+16V" TP_20-2136 116.397,196.243 r180 top value="Test Point"
TP10 "+5V" TP_20-2136 117.4,215.9 r0 top value="Test Point"
TP11 "UDC" TP_20-2136 116.789,155.511 r0 top value="Test Point"
TP12 "Ubridge" TP_20-2136 66.98,110.022 r0 top value="Test Point"
TP14 "~Zero_X" TP_20-2136 55.8,109.831 r270 top value="Test Point"
TP15 "IACp" TP_20-2136 81.15,102.8 r90 top value="Test Point"
TP17 "H2" "TEST POINT" 26.4,38.3 r90 top value=NA
TP18 "H1" "TEST POINT" 26.4,56.791 r90 top value=NA
TP19 "~Hbridge_" TP_20-2136 137.9,43.7 r270 top value="Test Point"
TP20 "GND" TP_20-313142 43.4,110.6 r180 top value="Test Point"
TP21 "GND" TP_20-313142 111,38.2 r180 top value="Test Point"
TP22 "IDCp" TP_20-2136 67.148,104.3 r180 top value="Test Point"
TP25 "GND" TP_20-313142 87.2,109.8 r180 top value="Test Point"
TR1 "CST306-2A" TRIAD_CST306-2A 20.054,47.556 r0 top
U6 "L6981NDR" SOIC-8 134.535,187.147 r90 top
U7 "L6981NDR" SOIC-8 133.835,207.927 r90 top
U8 "TS3021AILT" SOT23_5 56.102,146.356 r90 top
U9 "L6491D" SOIC_491D_STM 108.373,54.573 r0 top
U10 "TS507ILT" SOT23-5 83.608,148.62 r90 top
VR1 "MOV-14D561K" RESRR750W80L1650T600H2200 261.21,64.01 r270 top
VR2 "MOV-14D561K" RESRR750W80L1650T600H2200 190.6,101.381 r270 top

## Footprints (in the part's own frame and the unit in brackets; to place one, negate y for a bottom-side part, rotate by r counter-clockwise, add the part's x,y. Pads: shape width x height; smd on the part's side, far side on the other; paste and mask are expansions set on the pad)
BULGIN_PX0580/PC [mm]
  rect 3x3 hole 1.6: 1(-9.14,9.65)
  round 3 hole 1.6: 2(0,9.65) 3(9.14,9.65)
  round 3.4 hole 3.4 mask+0.127: MH1(20,0) MH2(-20,0)
  Keep-Out Layer circle w0.025: c-20,0 r2.462
  Keep-Out Layer circle w0.025: c20,0 r2.462
  silkscreen extent -24.9,-11.9 24.9,19.64, body extent -24.9,-11.9 24.9,18.7, height 27.8
CAP_0805J_AVX#1 [mil]
  rect 44x57 smd: 1(-35.5,0) 2(35.5,0)
  body extent 0,0 10,10, height 10
CAP_0805J_AVX#2 [mil]
  rect 44x57 smd paste+0 mask+0: 1(-35.5,0) 2(35.5,0)
  body extent 0,0 10,10, height 10
"Capacitor  Non-Polarised" [mm]
  round 2.7 hole 1.2: 1(0,0) 2(0,-22.5) 2(0,-27.5) 2(0,-37.5)
  silkscreen extent -12,-39.5 12,2, body extent -11.94,-39.5 11.94,2, height 24.5
CAPPRD1000W60D1300T550H1700 [mm] "Capacitor, Radial, Disc, 13.00X5.50 MM  Dia, Radial-2P"
  rect 1.404x1.404 / inner round 1.404 / far side rect 1.404x1.404 hole 0.904: 1(0,0)
  round 1.404 hole 0.904: 2(10,0)
  silkscreen extent -1.5,-2.75 11.5,2.75, body extent -1.5,-2.75 11.5,2.75, height 17
CAPRB1000W60L950T550H1350 [mm] "Capacitor, Radial, Disc, 9.50 MM  Dia, Radial-2P"
  round 1.6 hole 0.904: 1(0,0) 2(10,0)
  silkscreen extent 0.25,-2.75 9.75,2.75, body extent 0.25,-2.75 9.74,2.75, height 13.5
CAPRR1500W80L1800T500H1050A [mm] "CAPACITOR, RADIAL, 18 MM X 5 MM"
  round 2.7 hole 1.2: 1(0,0) 2(15,0)
  silkscreen extent -1.5,-2.5 16.5,2.5, body extent -1.5,-2.5 16.5,2.5, height 10.5
CAPRR1500W80L1800T800H1500A [mm] "CAPACITOR, RADIAL, 18 MM X 8 MM"
  round 2 hole 1.2: 1(0,0) 2(15,0)
  silkscreen extent -1.5,-4 16.5,4, body extent -1.5,-4 16.5,4, height 15
CAPRR2750W80L3150T1400H2450A [mm] "CAPACITOR, RADIAL, 31.5 MM X 14 MM"
  round 2.7 hole 1.2: 1(0,0) 2(27.5,0)
  silkscreen extent -2,-7 29.5,7, body extent -2,-7 29.5,7, height 24.5
CAPRR2750W80L3150T1600H3200A [mm] "CAPACITOR, RADIAL, 31.5 MM X 16 MM"
  round 2.7 hole 1.2: 1(0,0) 2(27.5,0)
  silkscreen extent -2,-8 29.5,8, body extent -2,-8 29.5,8, height 32
CC0805 [mm]
  rect 1.15x1.45 smd: 1(-0.9,0) 2(0.9,0)
  silkscreen extent -1,-1 1,1, body extent -1,-0.63 1,0.63, height 1.45
CC1206 [mm]
  rect 1.15x1.8 smd: 1(-1.5,0) 2(1.5,0)
  silkscreen extent -0.55,-0.8 0.55,0.8, body extent -1.6,-0.8 1.6,0.8, height 1.9
CC1210 [mm]
  rect 1.15x2.7 smd: 1(-1.5,0) 2(1.5,0)
  silkscreen extent -0.55,-1.25 0.55,1.25, body extent -1.6,-1.25 1.6,1.25, height 2.79
"CONNECTOR P2.5 MALE" [mm] "JST B2B-XH-A"
  round 1.8 hole 1: 1(-1.25,0) 2(1.25,0)
  silkscreen extent -3.7,-3.4 3.7,2.35, body extent -3.7,-3.4 3.7,2.35, height 7
"CONNECTOR P2.5 MALE 3WAY" [mm] "JST B3B-XH-A"
  round 1.8 hole 1: 1(-2.5,0) 2(0,0) 3(2.5,0)
  silkscreen extent -4.95,-3.4 4.95,2.35, body extent -4.95,-3.4 4.95,2.35, height 7
"Connector P5.08" [mm] "TE 1-917337-5"
  round 3.2 hole 2.2: 1(-5.715,-1.27) 2(5.715,-1.27)
  round 2.2 hole 1.2: 1(-2.54,0) 2(2.54,0)
  silkscreen extent -9.55,-4.7 9.55,4.7, body extent -9.54,-4.67 9.54,4.67, height 21.58
DO214AB-SMC [mm] "Molded Diode, 2-Leads, Body 6,88x5,85mm, IPC Medium Density"
  rect 2.55x3.15 smd: 1(-2.825,0) 2(2.825,0)
  silkscreen extent -4.5,-3.1 5.3,3.1, body extent -3.79,-3.08 3.79,3.08, height 2.65
DO214AC-SMA [mm]
  rect 1.6x1.8 smd: 1(-2.015,0) 2(2.015,0)
  silkscreen extent -3.1,-1.75 3.55,1.75, body extent -2.58,-1.3 2.5,1.28, height 2.65
"ELCAP SMD D5H5.8P1.5" [mm]
  rect 1.6x2.8 smd: 1(0,-2.15) 2(0,2.15)
  silkscreen extent -2.7,-2.7 2.7,2.6, body extent -2.65,-3 2.65,3, height 5.8
FUSEHOLDER_31.8201 [mm] "FUSE HOLDER, TH-2P"
  round 1.8 hole 1.3: 1(0,0) 2(22.5,0)
  silkscreen extent 0,-4.8 22.5,4.8, body extent -0.3,-4.8 22.8,4.8, height 11.5
HOLE_M3#1 [mm]
  round 6.7 hole 3.7 mask+0.127: 1(0,0)
  silkscreen extent -3.2,-3.2 3.2,3.2
HOLE_M3#2 [mm]
  round 6.7 hole 3.2 mask+0.127: 1(0,0)
  silkscreen extent -3.2,-3.2 3.2,3.2
KEYSTONE_7807 [mm] "PC SCREW TERMINAL, TH-6P"
  oval 4.2x3.8 hole 2.57: 1(-5.4,5.21) 1(-5.4,0) 1(-5.4,-5.21) 1(5.4,5.21) 1(5.4,0) 1(5.4,-5.21)
  silkscreen extent -3.63,-5.97 3.63,5.97, body extent -6.86,-5.97 6.86,5.97, height 11.82
LED_KPT-2012EC [mm] "LED, 2.00 MM X 1.25 MM, SMD-2P"
  rect 1.25x1.1 smd paste+0: 1(-1.175,0) 2(1.175,0)
  silkscreen extent -0.25,-0.63 0.25,0.63, body extent -1,-0.63 1,0.62, height 0.75
MULTICOMP_MCAP115018047A-221MU [mm] "IND, TOROIDAL, TH-2P"
  round 1.862 hole 1.354: 1(0,-6.5) 2(0,6.5)
  silkscreen extent -21.5,-7.5 21.5,7.5, body extent -21.5,-7.5 21.5,7.5, height 43
Net-Tie_0805_HV_NoOverlay#1 [mil] "0805_HV pads tied by 10mil copper trace which can be cut.  An 0805 part can be placed on pads."
  rect 60x100 on Mid1 paste-25 mask+1.97: 1(-40,0) 2(40,0)
  GND lines w100: 16,0 -16,0
  GND keep-out lines w1: 22,-30.91 22,30.91 ; 14.96,-30.91 -14.96,-30.91 ; -22,-30.91 -22,30.91 ; 14.96,30.91 -14.96,30.91
Net-Tie_0805_HV_NoOverlay#2 [mil] "0805_HV pads tied by 10mil copper trace which can be cut.  An 0805 part can be placed on pads."
  rect 60x100 smd paste-25 mask+1.97: 1(-40,0) 2(40,0)
  Top Layer lines w100: 16,0 -16,0
  Top Layer keep-out lines w1: 22,30.91 22,-30.91 ; 14.96,30.91 -14.96,30.91 ; -22,30.91 -22,-30.91 ; 14.96,-30.91 -14.96,-30.91
RC0805 [mm]
  rect 1.05x1.4 smd: 1(-0.95,0) 2(0.95,0)
  silkscreen extent -0.15,-0.63 0.15,0.63, body extent -1,-0.62 1,0.63, height 0.84
RC1206 [mm] "RES, SMD, 1.2K OHM,  5%, 1/4W, 1206"
  rect 1.05x1.75 smd: 1(-1.5,0) 2(1.5,0)
  silkscreen extent -0.6,-0.8 0.6,0.8, body extent -1.6,-0.8 1.6,0.8, height 0.84
RC2512 [mm]
  rect 1.1x3.4 smd: 1(-3.05,0) 2(3.05,0)
  silkscreen extent -2.15,-1.6 2.15,1.6, body extent -3.15,-1.6 3.15,1.6, height 0.7
RELAY_40.62.7.024.4000 [mil] "RELAY, TH-8P"
  round 62 hole 42: 11(295.28,-147.64) 12(100.39,-147.64) 14(492.13,-147.64) 21(295.28,147.64) 22(100.39,147.64) 24(492.13,147.64)
  rect 62x62 / inner round 62 / far side rect 62x62 hole 42: A1(-492.13,-147.64) A2(-492.13,147.64)
  silkscreen extent -630,-244 571,244, body extent -571,-244 571,244, height 984
"RES SMD 1206" [mm]
  rect 1.15x1.8 smd: 1(-1.45,0) 2(1.45,0)
  silkscreen extent -1.74,-1.08 1.74,1.08, body extent -1.63,-0.82 1.63,0.82, height 0.55
RESAD1508W70L1000D400A [mm] "RESISTOR, 2 PIN, AXIAL, 10MM L X 4MM DIA, TH"
  rect 1.484x1.484 / inner round 1.484 / far side rect 1.484x1.484 hole 0.984: 1(0,0)
  round 1.484 hole 0.984: 2(15.08,0)
  silkscreen extent 2.54,-2 12.54,2, body extent 2.54,-2 12.54,2, height 4
RESRR750W80L1650T600H2200 [mm] "RES, RADIAL, TH-2P"
  round 1.662 hole 1.154: 1(0,0) 2(7.5,0)
  silkscreen extent -4.5,-3 12,3, body extent -4.5,-3 12,3, height 22
SIP_GSIB2560-E3/45 [mm] "SIP, 30.00MM X 4.60 MM, TH-4P"
  rect 2.2x2.2 / inner round 2.2 / far side rect 2.2x2.2 hole 1.47: 1(0,0)
  round 2.2 hole 1.47: 2(10,0) 3(17.5,0) 4(25,0)
  silkscreen extent -3.21,-1.55 27.5,3.05, body extent -2.5,-1.55 27.5,3.05, height 20.3
SOIC-8 [mm] "SOIC, 8-Leads, Body 4,90x3,90mm, Pitch 1,27mm, IPC Medium Density"
  rect 1.8x0.6 smd: 1(-2.725,1.905)
  oval 1.8x0.6 smd: 2(-2.725,0.635) 3(-2.725,-0.635) 4(-2.725,-1.905) 5(2.725,-1.905) 6(2.725,-0.635) 7(2.725,0.635) 8(2.725,1.905)
  silkscreen extent -1.6,-2.5 1.6,2.5, body extent -3,-2.45 3,2.45, height 1.75
SOIC_491D_STM [mm]
  rect 1.455x0.558 smd: 1(-2.721,3.81) 2(-2.721,2.54) 3(-2.721,1.27) 5(-2.721,-1.27) 7(-2.721,-3.81) 9(2.721,-2.54) 10(2.721,-1.27) 11(2.721,0) 12(2.721,1.27) 14(2.721,3.81)
  oval 1.455x0.558 smd: 4(-2.721,0) 6(-2.721,-2.54) 8(2.721,-3.81) 13(2.721,2.54)
  silkscreen extent -2.12,-4.5 3.96,4.5, body extent -3.1,-4.37 3.1,4.37, height 1.76
SOT23-5 [mm] "IC, 1.6X2.9 MM, 0.95MM PITCH, SOT-23-5, SMD"
  rect 1.1x0.6 smd: 1(-1.3,0.95) 2(-1.3,0) 3(-1.3,-0.95) 4(1.3,-0.95) 5(1.3,0.95)
  silkscreen extent -2.68,-1.45 0.36,1.45, body extent -0.8,-1.45 0.8,1.45, height 1.45
SOT23_3 [mm] "SOT23, 3-Leads, Body 3.04x1.4mm, Pitch 0.95mm, IPC Medium Density"
  rect 0.6x1 smd: 1(-0.95,-1.2) 2(0.95,-1.2) 3(0,1.2)
  silkscreen extent -1.5,-0.7 1.5,0.7, body extent -1.46,-1.26 1.46,1.26, height 0.96
SOT23_5 [mm]
  rect 0.6x1.1 smd: 1(-0.95,-1.3) 2(0,-1.3) 3(0.95,-1.3) 4(0.95,1.3) 5(-0.95,1.3)
  silkscreen extent -1.65,-2.25 1.65,0.82, body extent -1.5,-1.5 1.5,1.5, height 1.3
"ST AUX SUPPLY" [mm]
  rect 1.6x1.6 hole 1: 1(2.5,30.5)
  round 1.6 hole 1: 2(2.5,35.58)
  rect 1.7x1.7 hole 1: 3(58.507,47.968)
  round 1.7 hole 1: 4(58.507,50.508) 5(55.967,47.968) 6(55.967,50.508) 7(53.427,47.968) 8(53.427,50.508) 9(50.887,47.968) 10(50.887,50.508) 11(48.347,47.968) 12(48.347,50.508) 13(45.807,47.968) 14(45.807,50.508)
  round 6.7 hole 3.7 unplated: MH(4,50) MH(58,4)
  rect 1.8x1.8 hole 1: ""(30,2.5)
  round 1.8 hole 1: ""(35.08,2.5)
  silkscreen extent 0,0 62,54, body extent 0,0 62,54, height 35.61
"ST MCU BOARD" [mm]
  rect 1.5x1.8 hole 1: 1(-19.05,1.27)
  oval 1.5x1.8 hole 1: 2(-19.05,-1.27) 3(-16.51,1.27) 4(-16.51,-1.27) 5(-13.97,1.27) 6(-13.97,-1.27) 7(-11.43,1.27) 8(-11.43,-1.27) 9(-8.89,1.27) 10(-8.89,-1.27) 11(-6.35,1.27) 12(-6.35,-1.27) 13(-3.81,1.27) 14(-3.81,-1.27) 15(-1.27,1.27) 16(-1.27,-1.27) 17(1.27,1.27) 18(1.27,-1.27) 19(3.81,1.27) 20(3.81,-1.27) 21(6.35,1.27) 22(6.35,-1.27) 23(8.89,1.27) 24(8.89,-1.27) 25(11.43,1.27) 26(11.43,-1.27) 27(13.97,1.27) 28(13.97,-1.27) 29(16.51,-1.27) 30(16.51,1.27) 31(19.05,-1.27) 32(19.05,1.27)
  round 6.7 hole 3.7 unplated: MH(-51.09,-1.51) MH(-51.09,54.49) MH(-51.09,90.49) MH(50.91,-1.51) MH(50.91,54.49) MH(50.91,90.49)
  silkscreen extent -55.09,-5.51 54.91,94.49, body extent -55.09,-5.51 54.91,94.49, height 21
TE_726386-2 [mm] "RES, RADIAL, TH-2P"
  round 2.38 hole 1.78: 1(-2.54,0) 1(2.54,0)
  silkscreen extent -4,-0.4 4,0.4, body extent -4,-0.4 4,0.4, height 10
"TEST POINT" [mm]
  round 5.2 hole 2.5: 1(0,0)
TO-247-3P [mm] "IC, TO-247P, 5.56MM PITCH, TH-3P"
  oval 3.2x3.9 hole 1.779: 1(0,0) 2(5.56,0) 3(11.12,0)
  silkscreen extent -3.18,-1.92 13.37,2.78, body extent -2.25,-1.92 13.37,2.78, height 24.75
TP_20-2136 [mm] "TEST POINT, BLACK, TH"
  round 1.8 hole 1.3: 1(0,0)
  silkscreen extent -1.5,-1.5 1.5,1.5, body extent -1.49,-1.5 1.5,1.5, height 5.4
TP_20-313142 [mm] "TEST POINT, GREEN,  TH"
  round 1.8 hole 1.3: 1(0,0)
  silkscreen extent -1.5,-1.5 1.5,1.5, body extent -1.49,-1.5 1.5,1.5, height 5.4
TRIAD_CST306-2A [mil] "CURRENT SENSE TRANSFORMER, TH-2P"
  rect 62x62 hole 42: 1(0,0)
  round 62 hole 42: 3(500,0)
  silkscreen extent -127,-192 595,192, body extent -95,-193 595,192, height 1693
VSMP_1206 [mm] "Vishay Recommended"
  rect 1.3x1.85 smd: 1(-1.45,0) 2(1.45,0)
  silkscreen extent -2.4,-1.21 2.4,1.21, body extent -1.66,-0.85 1.66,0.85, height 0.64
VSMP_2512 [mm] "Vishay Recommended"
  rect 1.8x3.23 smd: 1(-2.8,0) 2(2.8,0)
  silkscreen extent -1.63,-1.85 1.6,1.83, body extent -3.22,-1.73 3.22,1.73, height 0.64
WE-PD_1260 [mm] "SMT Shielded Power Inductor, 2-leads, body 12x12mm"
  rect 5.4x3 smd: 1(0,-5) 2(0,5)
  silkscreen extent -6.25,-7.02 6.25,6.25, body extent -6,-6 6,6, height 5.66
WE_7448051012 [mm] "CHOKE, WE-CMBNC, 34X23X33 MM, TH-4P"
  rect 2.1x2.1 / inner round 2.1 / far side rect 2.1x2.1 hole 1.6: 1(0,0)
  round 2.1 hole 1.6: 2(25,0) 3(25,15) 4(0,15)
  silkscreen extent -5.23,-4 29.5,19, body extent -2.84,-2.8 27.84,17.8, height 30.25

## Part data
C1: library part "Capacitor P_2", "Cap Aluminum 47uF 16V 20% (5 X 5.8mm) SMD 0.36 Ohm 240mA 2000 hr 105°C Embossed T/R", Case/Package=SMD/SMT, ESR (Equivalent Series Resistance)=360mR, Leakage Current=7.5uA, Manufacturer 1=Panasonic, Manufacturer Part Number 1=EEE-FPC470UAR, Max Operating Temperature=105°C, Min Operating Temperature=-55°C, Package Quantity=1000, Ratings=AEC-Q200, Ripple Current=240mA, Supplier Part Number 1=2408640, Tolerance=20%, Voltage=16V
C2 C70: library part "CAP NP", "Capacitor  1210", Dielectric=X7R, Manufacturer 3=AVX, Voltage=50V
C3: library part "CAP NP", "Capacitor  Non-Polarised", Dielectric=PP, Manufacturer 1=WIMA, MPN 1=FKP1O121004F00KSSD, Supplier Part Number 1=1890192, Voltage=1kV
C4 C48 C54 C55 C56 C58 C59 C61 C65 C66 C67 C68 C80 C81 C83 C84 C86: library part "CAP NP", "Capacitor  0805", Dielectric=X7R, Manufacturer 1=VISHAY, MPN 1=VJ0805Y104KXACW1BC, Supplier Part Number 1=2407344, Voltage=50V
C29 C32 C36 C37 C41 C88 C93 C94: library part 08051A561JAT2A, "No Description Available"
C33 C34 C35 C38 C39 C40 C89 C91 C92: library part 12061C104KAT2A, "No Description Available"
C42 C43 C44 C45: library part "CAP NP", "Capacitor  Non-Polarised", Dielectric=X2, Manufacturer 1=EPCOS, Manufacturer 2=KEMET, MPN 1=B32924C3225M000, MPN 2=R463R422050M1K, MPN 3=BFC233820225, Supplier Part Number 1=1112849, Voltage=305Vac
C46 C47: library part "CAP NP", "Capacitor  Non-Polarised", Dielectric=Y1, Manufacturer 1=VISHAY, MPN 1=VY1472M51Y5VQ63V0, Supplier Part Number 1=2677044, Voltage=500Vac
C49 C50 C51 C52: library part "CAP NP", "Capacitor  1206", Dielectric=NP0, Manufacturer 1=VISHAY, MPN 1=885342008011, Supplier Part Number 1=2812538, Voltage=2kV
C57 C60: library part "CAP NP", "Capacitor  0805", Dielectric=X7R, Manufacturer 1=VISHAY, MPN 1=VJ0805Y222JXAPW1BC, Supplier Part Number 1=3298217, Voltage=50V
C69 C87: library part "CAP NP", "Capacitor  1210", Dielectric=X7R, Manufacturer 1=MURATA, Manufacturer 3=AVX, MPN 1=12105C475KAT2A, Supplier Part Number 1=1658891, Voltage=50V
C72 C73 C78 C79: library part "CAP NP", "Capacitor  Non-Polarised", Dielectric=PP, Manufacturer 1=KEMET, MPN 1=R73QW3160ZMK0J, Supplier Part Number 1=80-R73QW3160ZMK0J, Voltage=400Vac
C74 C77: library part "CAP NP", "Capacitor  Non-Polarised", Dielectric=PP, Manufacturer 1=WIMA, MPN 1=FKP1R014704D00KSSD, Supplier Part Number 1=1890199, Voltage=1.25kV
C75: library part "CAP NP", "Capacitor  Non-Polarised", Manufacturer 1=EPCOS, MPN 1=B32674D6335K000, Supplier Part Number 1=882-9395, Voltage=650V
C76: library part "CAP NP", "Capacitor  Non-Polarised", Dielectric=X2, Manufacturer 1=EPCOS, Manufacturer 2=Vishay, MPN 1=B32922C3104M000, MPN 2=BFC233820104, Supplier Part Number 1=2728566, Voltage=305Vac
C82: library part "CAP NP", "Capacitor  Non-Polarised", Dielectric=Y1, Manufacturer 1=VISHAY, MPN 1=VY1222M37Y5VQ63V0, Supplier Part Number 1=2677041, Voltage=500Vac
CM1 CM2: "Common Mode Power Line Choke", Manufacturer 1="WURTH ELEKTRONIK", MPN 1=7448051012, Supplier Part Number 1=732-5597-ND
D1: library part "DIODE LED", "LED", Colour=Red, Manufacturer 1=KINGBRIGHT, Supplier Part Number 1=2099239
D22 D23 D25 D26 D34 D38: library part "Diode Dual BAT54S", "Dual series Schottky Diode", Manufacturer 1=STMicroelectronics, Manufacturer Part Number 1=BAT54SFILM, Supplier Part Number 1=9801510
D27 D28 D29 D36: library part DIODE, "Diode", Current=1A, Manufacturer 1=ST, MPN 1=STTH1R06A, Supplier Part Number 1=1697520, Voltage=600V
D30 D33: library part "Diode STPS1L30A", "Small Signal Schottky Diode", Average Rectified Current=1A, Case/Package=SMA, Forward Voltage=395mV, Manufacturer 2=STMicroelectronics, Max Forward Surge Current (Ifsm)=75A, Max Operating Temperature=150°C, Max Repetitive Reverse Voltage (Vrrm)=30V, Max Reverse Current=200uA, Min Operating Temperature=-65°C, Package Quantity=1, Supplier Part Number 1=9907491
D31 D35: library part "Diode STPS1L30A", "Small Signal Schottky Diode", Average Rectified Current=1A, Case/Package=SMA, Forward Voltage=395mV, Manufacturer 2=STMicroelectronics, Manufacturer Part Number 2=STPS1L30A, Max Forward Surge Current (Ifsm)=75A, Max Operating Temperature=150°C, Max Repetitive Reverse Voltage (Vrrm)=30V, Max Reverse Current=200uA, Min Operating Temperature=-65°C, Package Quantity=1, Supplier Part Number 1=2353671
D32: library part BRIDGE, "Bridge Rectifier", Current=25A, Manufacturer 1=VISHAY, MPN 1=GSIB2560-E3/45, Supplier Part Number 1=9549749, Voltage=600V
D37: library part "DIODE LED", "LED", Colour=Red, Manufacturer 1=KINGBRIGHT, Supplier Part Number 1=2099236
F1: library part F, "FuseHolder 5x20mm", Supplier Part Number 1=1162740
J1 J10 J19: library part "TEST POINT", Supplier Part Number 1=4215618
J4: library part HEADER3, "Power Entry Connector, Plug, 250 VAC, 10 A", Manufacturer 1=Bulgin, MPN 1=PX0580PC, Supplier Part Number 1=313853
J8: library part HEADER2, "3 pin JST connector", Manufacturer 1=JST, MPN 1=B2B-XH-A, Package=TBD, Supplier Part Number 1=1516276
J9 J20: library part HEADER2, "3 pin JST connector", Manufacturer 1=JST, MPN 1=B2B-XH-A, Supplier Part Number 1=1516276
J12 J16 J18: library part 1729128, "TE Connectivity 1-917337-5", Manufacturer_Part_Number=1-917337-5, Mfr_Name="TE Connectivity", Supplier Part Number 1=3398356
J13 J14: library part HEADER1, "Screw on Terminal", Supplier Part Number 1=2909401
K1: library part "RELAY-DPDT 2CO", "Dual-Pole Dual-Throw Relay", Current=10A, Manufacturer 1=Finder, MPN 1=40.62.7.024.4000, Supplier Part Number 1=182-9781
L3: library part 744771147, "Fixed Ind 47UH 2.21A 75 Mohm SMD", Manufacturer 1="Wurth Electronics", Supplier Part Number 1=1635910
L4: library part MSS1048T-224KL, "General Purpose Inductor, 33uH, 20%, 1 Element, Ferrite-Core, SMD, 4747", Manufacturer 1="Wurth Electronics", Manufacturer Part Number 1=744771133, Supplier Part Number 1=2082608
L5: library part "INDUCTOR FERRITE", "Inductor 200mH", Supplier Part Number 1=1864222
NT1: library part NET-TIE, "NET-TIE"
P7: library part "ST inverter MCU Board", "TSW-116-07-G-D"
P9 P10 P11: "3 pin JST connector", Mfr_Name=JST
P12: library part "ST inverter AUX supply board", "2 x TSW-103-07-G-S-002 + TSW-106-07-G-D"
Q2 Q3 Q6 Q7: library part "NPN 2STR1160", "NPN Bipolar Transistor", Case/Package=SOT-23, Collector Base Voltage (VCBO)=60V, Collector Emitter Saturation Voltage=430mV, Emitter Base Voltage (VEBO)=5V, Manufacturer 1=STMicroelectronics, Max Collector Current=1A, Max Operating Temperature=150°C, Max Power Dissipation=500mW, Min Operating Temperature=-65°C, Package Quantity=1, Supplier Part Number 1=511-2STR1160
Q4 Q5: library part IKW30N60H3, "100 A, 1.5 V, 300 W, 650 V", Current=150A, Package=TO247_VFET, Supplier Part Number 1=3011597, Voltage=650V
R1 R6 R24 R27 R31 R32 R33 R36 R37 R43 R52 R55 R56 R58 R59 R61 R62 R63 R64 R66 R67 R68 R69 R70 R71 R72 R73 R75 R78 R79 R80 R82 R83 R84 R85 R86 R87 R88 R89 R91 R92 R93 R94 R95 R96 R98 R99 R101 R102 R103 R104 R105 R106 R110 R111 R112 R113 R114 R115 R118 R119 R120 R122: library part RESISTOR, "RESISTOR 0805"
R2 R3 R4 R74 R76 R77: library part RES, "Resistor 1206", Rated Power=1W, Supplier Part Number 1=9236619, Tolerance=1%
R5 R81 R107 R108: library part RES, "Resistor 2512", Rated Power=1W, Supplier Part Number 1=NA
R7 R38 R39 R40 R41 R44 R45 R47 R48 R49 R50 R53 R54: library part RESISTOR, "Res Thick Film 1206 681K Ohm 1% 0.25W(1/4W) ±200ppm/C Epoxy Pad SMD T/R", Case Code (Imperial)=1206, Case Code (Metric)=3216, Manufacturer 1=Yageo, Manufacturer Part Number 1=RV1206FR-07681KL, Max Operating Temperature=155°C, Max Power Dissipation=250mW, Min Operating Temperature=-55°C, Package Quantity=1, Supplier Part Number 1=603-RV1206FR-07681KL, Temperature Coefficient=200ppm/°C, Tolerance=1%, Voltage Rating=500V
R8: library part RES, "CRCW Series 1206 0.25 W 0 Ohm Jumper Surface Mount Thick Film Chip Resistor", Manufacturer 2=Vishay, Manufacturer Part Number 2=CRCW12060000Z0EA
R34: library part RESISTOR, "Resitor Axial", Manufacturer 1=VISHAY, Rated Power=500mW, Voltage=3500V
R35: library part RESISTOR, "Resitor Axial", Manufacturer 1=VISHAY, MPN 1=VR37000001004JA100, Rated Power=500mW, Voltage=3500V
R42 R46: library part RESISTOR, "Resistor 1206", Manufacturer 1=VISHAY, MPN 1=CRCW120668K0FKEA, Supplier Part Number 1=2139575, Tolerance=1%, Voltage=200V
R90: library part RES, "Resistor 2512", Rated Power=2W, Supplier Part Number 1=652-CRM2512JXR680ELF, Tolerance=5%
R97 R100: library part RES, "Resistor 2512", Rated Power=3W, Supplier Part Number 1=2321759, Tolerance=1%
TP1 TP2 TP3 TP9 TP10 TP11 TP12 TP14 TP15 TP19 TP22: library part TESTP, "Test Point", Colour=Black, Supplier Part Number 1=8731195
TP17 TP18: library part "TEST POINT", Supplier Part Number 1=NA
TP20 TP21 TP25: library part TESTP, "Test Point", Colour=Green, Supplier Part Number 1=8731217
TR1: library part 56050C_5, "Current Transfomer", Supplier Part Number 1=237-1106-ND
U6 U7: library part "Voltage Regulator L6981", "DC-DC Switching Synchronous Adjustable Buck Converter", Manufacturer 1=STMicroelectronics, Manufacturer Part Number 1=L6981CDR, Supplier Part Number 1=497-L6981CDRCT-ND
U8: library part "Comparator TS3021AILT", "Single OPAMP 5 pin package", Case/Package=SOT-23, Manufacturer 1=STMicroelectronics, Max Operating Temperature=125°C, Max Supply Voltage=5V, Min Operating Temperature=-40°C, Min Supply Voltage=1.8V, Supplier Part Number 1=2851920
U9: "Half Bridge Driver"
U10: library part MCP6561, "1.8V Low Power Push-Pull Output Comparator", Package=SOT23_5leadC, Supplier Part Number 1=497-8118-1-ND
VR1 VR2: library part RVA, "Varistor 14mm disc, 350 Vrms, Vdc=560V@1mA,  Pitch=7.5mm", Rated Power=125J, Supplier Part Number 1=2250944, Voltage=350V

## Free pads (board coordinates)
  round 0.508 on Mech11: 1(151.602,-29.68)
  round 2 hole 1.2: ""(112,75.7) ""(114.5,75.7) ""(129.9,17.3) ""(129.9,19.8) ""(129.9,51.3) ""(129.9,53.8)
  round 0.1 hole 1 slot 5 at 90 deg unplated mask+0.102: ""(234.976,123.575) ""(234.976,131.075)

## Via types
v1: diameter 0.8, hole 0.4, Top Layer to Bottom Layer, tented both sides, 234 vias
v2: diameter 0.6, hole 0.3, Top Layer to Bottom Layer, tented both sides, 2 vias

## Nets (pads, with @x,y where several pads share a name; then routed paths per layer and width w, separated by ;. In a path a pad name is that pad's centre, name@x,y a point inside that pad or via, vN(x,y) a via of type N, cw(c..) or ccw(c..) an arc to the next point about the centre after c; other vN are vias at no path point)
16V_Enable: P7.16 R119.2 | length 129
  Top Layer w0.508: v1(56.07,139.167) 56.052,139.148 56.052,129.6 P7.16@57.31,128.342 ; R119.2@142.458,190.843 v1(142.458,192.412)
  Bottom Layer w0.508: v1(56.07,139.167) 66.171,139.167 74.752,147.748 74.752,155.169 92.547,172.964 128.641,172.964 142.458,186.78 v1(142.458,192.412)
